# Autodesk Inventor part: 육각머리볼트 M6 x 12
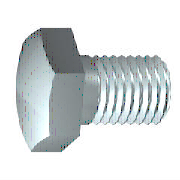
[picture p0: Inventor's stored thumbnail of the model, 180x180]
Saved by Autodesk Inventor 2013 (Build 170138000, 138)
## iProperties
IsCustomPart: 1
Created: 2012-02
Part Number: 육각머리볼트 M6 x 12
Material: 스테인리스강
Description: 6각 머리 나사
Document SubType Name: Modeling
Standard: ISO 4017
Designer: mdu-01
Standard Revision: Third edition 1999-08-15
Standards Organization: ISO
Language: ko-KR
Size Designation: M6 x 12
Categories: <MemberInstance><Categories><Category DisplayName="조임쇠" InternalName="e4da775c-781d-43d5-af7c-5136215cf5a6" Mnemonic="FSTN"><Category DisplayName="볼트" InternalN
Density: 7.75 g/cm^3
Author: mdu-01
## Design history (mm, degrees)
sketch "스케치1"
  geometry: L1 (0, 4.44)-(0, 3); L2 (1.15, 3)-(12, 3); L3 (12, 3)-(12, 0); L4 (12, 0)-(-0.5, 0); L5 (-3, 0)-(14.5, 0) reference; L6 (-0.5, 0)-(-0.5, 4.44); L7 (-0.5, 4.44)-(0, 4.44); L8 (1.15, 3)-(0.536, 3); L9 (0.536, 3)-(0, 3); L10 (0, -0.888)-(0, 5.328) reference
  constraints: 16 end point, 2 collinear, 2 perpendicular, 1 parallel
  dimensions: "d0" = 12 distance between parallel lines of L3 L1 (= NLG); "d1" = 10.85 distance from line of L2.start L3 (= GEL); "d2" = 6 diameter of L2 L4 (= GD); "d9" = 0.5001 distance between parallel lines of L6 L1 (computed from SD); "d10" = 8.88 diameter of L7 L4 (= SD2); "d13" = 0.61355 distance of L2.start L8.end (computed from GAL); "d14" = 6 diameter of L9 L4 (= BDM)
revolve "본체" sketch "스케치1" stored, may be unused: angle "d12" = 90 deg
sketch "스케치2"
  geometry: L1 (0, 5.774)-(5, 2.887); L2 (5, 2.887)-(5, -2.887); L3 (5, -2.887)-(0, -5.774); L4 (0, -5.774)-(-5, -2.887); L5 (-5, -2.887)-(-5, 2.887); L6 (-5, 2.887)-(0, 5.774); 2 further points
  constraints: 12 end point, 1 coincident, 1 vertical, 11 other
  dimensions: "d11" = 10 distance between parallel lines of L5 L2 (= SW)
extrude "머리" join sketch "스케치2" distance "d3" = 3.5 (= KOH - SD); taper "d4" = 0 deg
sketch "스케치4"
  geometry: L1 (-4, 5)-(-4, 5.774); L2 (-4, 5.774)-(-3.554, 5.774); L3 (-3.554, 5.774)-(-4, 5); L4 (-4.7, 0)-(0.2, 0) reference; L5 (-0.5, 5.774)-(-4, 5.774) reference; L6 (-4, 2.887)-(-4, 5.774) reference
  constraints: 6 end point, 2 collinear, 1 perpendicular, 1 vertical
  dimensions: "d5" = 30 deg angle of L3 L1 (= ANG1); "d19" = 10 diameter of L1.start L4 (= SW0)
revolve "모따기1" sketch "스케치4" stored, may be unused: angle "d21" = 90 deg
workplane "Work Plane1"
body "Solid1"
feature "스레드" dims "d15" = 10.85 (= GEL), "d16" = 0
chamfer "모따기2" distance "d6" = 0.61345 (= -0.5 x SPD + 0.5 x GD); stored, may be unused: second distance "d7" = 0.61355 (computed from GUL), angle "d55" = 45 deg
other parameters: "NLG" = 12 [user parameter; used in 1 equation term], "GD" = 6 (= NND) [user parameter; used in 2 equation terms], "BDM" = 6 (= NND) [user parameter; used in 1 equation term], "KOH" = 4 [user parameter; used in 1 equation term], "GEL" = 10.85 [user parameter; used in 2 equation terms], "SW" = 10 [user parameter; used in 2 equation terms], "SW0" = 10 (= SW) [user parameter; used in 1 equation term], "SPD" = 4.7731 (= NND - 1.2269 x PTC) [user parameter; used in 1 equation term], "SD2" = 8.88 [user parameter; used in 2 equation terms], "SD" = 0.5 [user parameter; used in 2 equation terms], "ANG1" = 30 deg [user parameter; used in 1 equation term], "GAL" = 0.61345 (= 0.61345 x PTC) [user parameter; used in 1 equation term], "GUL" = 0.61345 (= 0.61345 x PTC) [user parameter; used in 1 equation term], "d8" = 0, "RR" = 0.25 [user parameter], "d57" = 0, "d58" = 0, "GD1" = 4.7731 (= THREADDIA - 1.2269 x PTC) [user parameter], "THREADDIA" = 6 [user parameter; used in 1 equation term], "SDH" = 8.88 (= SD2) [user parameter], "SDHG" = 3 [user parameter], "TOA" = 30 deg [user parameter], "PTC" = 1 [user parameter; used in 5 equation terms], "NND" = 6 [user parameter; used in 3 equation terms], "E0" = 11.55 [user parameter]
